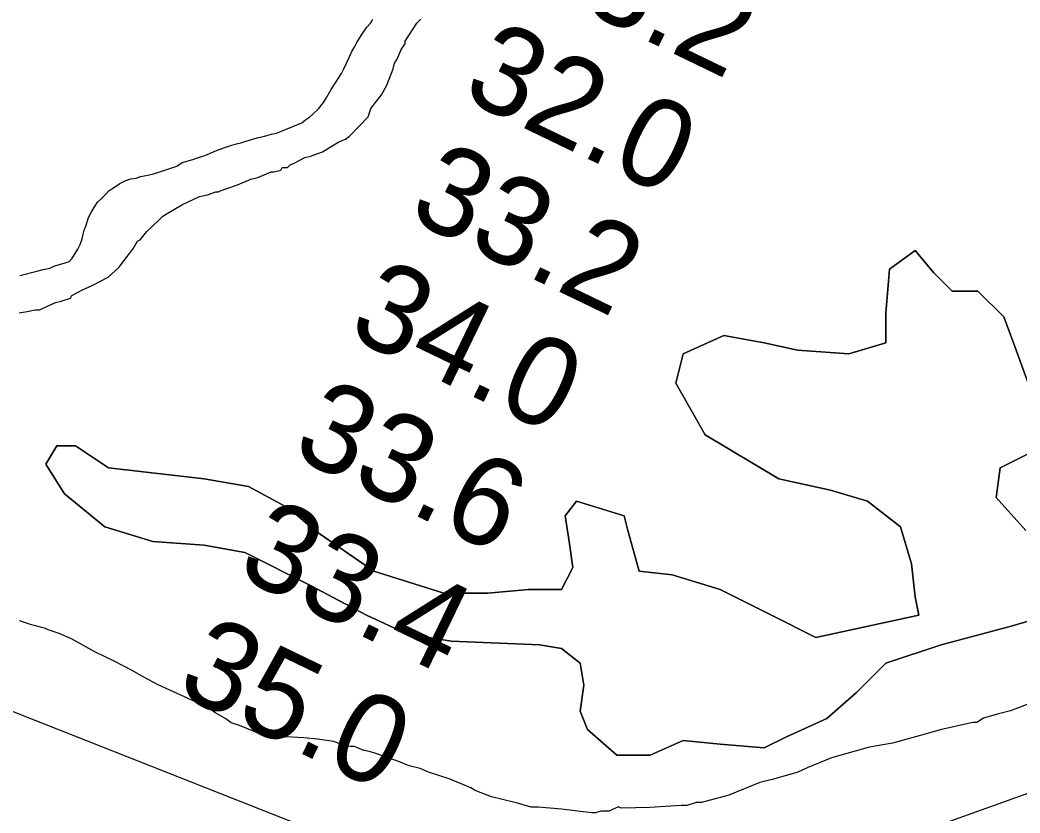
# Model space of a CAD drawing. Extents: x 3219052 to 3256913, y 800770 to 826146.
# Drawn here: x 3237861 to 3238618, y 811124 to 811725 of the extents above; entities that cross this region are included whole.
import ezdxf

# ---------------------------------------------------------------- set-up
doc = ezdxf.new("R2010")
doc.units = 0
for name, color, linetype in [('V-LEVE-TOET', 7, 'Continuous'), ('V-RIVR-RANG', 7, 'Continuous'), ('V-SITE-VEGE', 7, 'Continuous'), ('V-TOPO-SHOR', 7, 'Continuous')]:
    doc.layers.add(name, color=color, linetype=linetype)

msp = doc.modelspace()

# ---------------------------------------------------------------- linework, layer by layer
at = {"layer": 'V-LEVE-TOET'}
for points in [[(3240582.342, 810973.949), (3240012.289, 811195.518), (3239640.372, 811323.9770000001), (3239605.614, 811332.902), (3239570.251, 811345.123), (3239539.09, 811351.06), (3239508.235, 811354.603), (3239472.887, 811357.837), (3239436.0470000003, 811357.175), (3239400.705, 811357.415), (3239363.569, 811355.2540000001), (3239330.921, 811355.199), (3239297.078, 811353.343), (3239268.634, 811348.8030000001), (3239238.991, 811343.361), (3239077.918, 811304.15), (3238719.921, 811173.252), (3238449.923, 811076.349)], [(3238182.165, 811071.7000000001), (3237860.271, 811198.746), (3237814.414, 811217.536), (3237784.448, 811226.4720000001), (3237756.583, 811232.116), (3237732.015, 811236.265), (3237708.346, 811240.419), (3237688.88, 811239.188), (3237662.825, 811237.3470000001), (3237316.042, 811205.908), (3236864.697, 811191.961), (3236556.232, 811171.966), (3236455.3140000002, 811160.1140000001), (3236418.184, 811154.96), (3236209.219, 811099.193)]]:
    msp.add_lwpolyline(points, dxfattribs=at)
at = {"layer": 'V-SITE-VEGE'}
for points in [[(3237860.046, 811502.831), (3237866.214, 811503.98), (3237872.383, 811505.1290000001), (3237875.477, 811505.188), (3237880.595, 811507.349), (3237887.757, 811510.5800000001), (3237891.864, 811511.6900000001), (3237899.046, 811513.89), (3237900.037, 811515.973), (3237908.211, 811520.255), (3237915.373, 811523.4890000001), (3237927.632, 811529.912), (3237935.7460000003, 811537.2880000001), (3237943.803, 811547.762), (3237946.818, 811551.946), (3237949.8140000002, 811557.16), (3237951.858, 811558.231), (3237956.898, 811564.519), (3237966.024, 811572.944), (3237969.059, 811576.1), (3237972.114, 811578.2220000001), (3237983.344, 811584.628), (3237996.633, 811591.071), (3238002.804, 811592.22), (3238008.954, 811594.4010000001), (3238011.0160000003, 811594.4400000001), (3238013.058, 811595.511), (3238025.358, 811599.871), (3238035.594, 811604.192), (3238040.733, 811605.323), (3238050.969, 811609.644), (3238053.0330000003, 811609.683), (3238058.169, 811610.814), (3238059.163, 811612.8960000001), (3238063.287, 811612.974), (3238065.311, 811615.078), (3238068.387, 811616.167), (3238076.558, 811620.452), (3238080.667, 811621.56), (3238089.8910000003, 811624.8300000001), (3238094.988, 811628.023), (3238102.13, 811632.287), (3238107.248, 811634.448), (3238110.303, 811636.569), (3238124.469, 811651.286), (3238126.415, 811657.512), (3238134.47, 811667.986), (3238138.4590000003, 811675.283), (3238143.38, 811687.757), (3238144.335, 811691.904), (3238146.338, 811695.0380000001), (3238149.295, 811702.316), (3238152.312, 811706.5), (3238152.273, 811708.5650000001), (3238161.3000000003, 811722.149), (3238164.336, 811725.3030000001)], [(3238625.039, 811446.734), (3238613.886, 811477.4230000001), (3238605.518, 811499.7440000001), (3238585.994, 811519.274), (3238566.475, 811519.274), (3238552.532, 811533.223), (3238538.5870000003, 811549.964), (3238519.066, 811536.015), (3238516.276, 811502.534), (3238516.276, 811480.215), (3238488.389, 811471.845), (3238449.346, 811474.636), (3238424.245, 811480.215), (3238393.568, 811485.794), (3238362.8910000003, 811471.845), (3238357.315, 811449.525), (3238379.625, 811410.464), (3238435.403, 811376.985), (3238474.444, 811368.617), (3238502.3310000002, 811360.247), (3238527.432, 811340.715), (3238535.798, 811312.817), (3238538.5870000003, 811287.707), (3238541.377, 811273.758), (3238463.288, 811257.018), (3238429.826, 811273.758), (3238390.781, 811293.29), (3238354.525, 811304.447), (3238329.427, 811307.237), (3238321.061, 811337.9280000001), (3238318.271, 811349.085), (3238282.018, 811360.247), (3238273.6520000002, 811349.085), (3238276.4390000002, 811329.558), (3238279.228, 811310.028), (3238270.862, 811293.29), (3238245.762, 811293.29), (3238215.085, 811290.496), (3238181.6210000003, 811290.496), (3238128.633, 811307.237), (3238084.011, 811337.9280000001), (3238064.489, 811354.666), (3238033.812, 811371.407), (3238000.35, 811376.985), (3237927.839, 811385.356), (3237902.74, 811402.096), (3237888.796, 811402.096), (3237880.43, 811388.149), (3237894.372, 811365.826), (3237925.049, 811340.715), (3237961.305, 811329.558), (3238000.35, 811326.7660000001), (3238031.025, 811321.188), (3238081.224, 811296.077), (3238123.054, 811273.758), (3238153.731, 811259.809), (3238187.197, 811254.228), (3238254.128, 811251.439), (3238270.862, 811248.645), (3238284.805, 811237.488), (3238287.594, 811220.748), (3238284.805, 811201.22), (3238290.386, 811187.269), (3238312.6950000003, 811167.7390000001), (3238337.793, 811167.7390000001), (3238362.8910000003, 811178.899), (3238390.781, 811176.109), (3238424.245, 811173.322), (3238440.9790000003, 811181.688), (3238471.656, 811195.639), (3238493.965, 811215.169), (3238516.276, 811237.488), (3238558.109, 811251.439), (3238611.097, 811265.388), (3238658.506, 811279.337)], [(3238329.427, 811307.237), (3238354.525, 811304.447), (3238390.781, 811293.29), (3238429.826, 811273.758), (3238463.288, 811257.018), (3238541.377, 811273.758), (3238538.5870000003, 811287.707), (3238535.798, 811312.817), (3238527.432, 811340.715), (3238502.3310000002, 811360.247), (3238474.444, 811368.617), (3238435.403, 811376.985), (3238379.625, 811410.464), (3238357.315, 811449.525), (3238362.8910000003, 811471.845), (3238393.568, 811485.794), (3238424.245, 811480.215), (3238449.346, 811474.636), (3238488.389, 811471.845), (3238516.276, 811480.215), (3238516.276, 811502.534), (3238519.066, 811536.015), (3238538.5870000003, 811549.964), (3238552.532, 811533.223), (3238566.475, 811519.274), (3238585.994, 811519.274), (3238605.518, 811499.7440000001), (3238613.886, 811477.4230000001), (3238625.039, 811446.734)], [(3238658.506, 811279.337), (3238611.097, 811265.388), (3238558.109, 811251.439), (3238516.276, 811237.488), (3238493.965, 811215.169), (3238471.656, 811195.639), (3238440.9790000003, 811181.688), (3238424.245, 811173.322), (3238390.781, 811176.109), (3238362.8910000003, 811178.899), (3238337.793, 811167.7390000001), (3238312.6950000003, 811167.7390000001), (3238290.386, 811187.269), (3238284.805, 811201.22), (3238287.594, 811220.748), (3238284.805, 811237.488), (3238270.862, 811248.645), (3238254.128, 811251.439), (3238187.197, 811254.228), (3238153.731, 811259.809), (3238123.054, 811273.758), (3238081.224, 811296.077), (3238031.025, 811321.188), (3238000.35, 811326.7660000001), (3237961.305, 811329.558), (3237925.049, 811340.715), (3237894.372, 811365.826), (3237880.43, 811388.149), (3237888.796, 811402.096), (3237902.74, 811402.096), (3237927.839, 811385.356), (3238000.35, 811376.985), (3238033.812, 811371.407), (3238064.489, 811354.666), (3238084.011, 811337.9280000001), (3238128.633, 811307.237), (3238181.6210000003, 811290.496), (3238215.085, 811290.496), (3238245.762, 811293.29), (3238270.862, 811293.29), (3238279.228, 811310.028), (3238276.4390000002, 811329.558), (3238273.6520000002, 811349.085), (3238282.018, 811360.247), (3238318.271, 811349.085), (3238321.061, 811337.9280000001), (3238329.427, 811307.237)], [(3238625.039, 811396.515), (3238602.728, 811385.356), (3238599.941, 811363.036), (3238622.25, 811337.9280000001)], [(3238622.25, 811337.9280000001), (3238599.941, 811363.036), (3238602.728, 811385.356), (3238625.039, 811396.515)], [(3238143.012, 811164.608), (3238131.5840000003, 811168.517), (3238125.358, 811170.463), (3238121.213, 811171.415), (3238113.932, 811174.373), (3238110.838, 811174.313), (3238105.66, 811175.247), (3238098.382, 811178.204), (3238085.963, 811180.031), (3238075.631, 811180.8690000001), (3238062.202, 811181.643), (3238050.856, 811181.43), (3238043.596, 811183.353), (3238026.9560000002, 811190.261), (3238020.728, 811192.207), (3238016.54, 811195.221), (3238008.19, 811200.2220000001), (3238000.874, 811205.242), (3237991.511, 811209.193), (3237965.487, 811221.079), (3237954.026, 811227.051), (3237945.677, 811232.052), (3237932.129, 811239.018), (3237917.552, 811245.965), (3237899.8200000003, 811255.944), (3237890.4590000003, 811259.895), (3237882.15, 811262.832), (3237880.0670000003, 811263.823), (3237868.66, 811266.703), (3237860.3510000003, 811269.639)], [(3238636.375, 811211.134), (3238610.767, 811201.359), (3238601.522, 811199.121), (3238590.236, 811195.809), (3238585.136, 811192.618), (3238582.042, 811192.559), (3238557.386, 811186.931), (3238546.097, 811183.621), (3238521.46, 811176.961), (3238508.09, 811174.645), (3238502.952, 811173.514), (3238475.24, 811165.765), (3238456.81, 811158.191), (3238449.649, 811154.96), (3238438.362, 811151.648), (3238430.15, 811149.43), (3238420.9050000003, 811147.189), (3238397.357, 811137.4550000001), (3238376.828, 811131.905), (3238372.701, 811131.827), (3238365.521, 811129.628), (3238361.394, 811129.5480000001), (3238337.691, 811128.067), (3238316.031, 811127.656), (3238313.946, 811128.647), (3238308.828, 811126.486), (3238306.786, 811125.415), (3238300.595, 811125.2980000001), (3238296.491, 811124.188), (3238293.394, 811124.1290000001), (3238270.6410000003, 811126.791), (3238253.069, 811128.522), (3238247.912, 811128.424), (3238237.539, 811131.322), (3238234.424, 811132.294), (3238217.844, 811136.108), (3238205.367, 811141.029), (3238202.236, 811143.032), (3238185.596, 811149.9400000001), (3238170.023, 811154.804), (3238163.774, 811157.78), (3238155.484, 811159.684), (3238148.2060000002, 811162.6460000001), (3238143.012, 811164.608)]]:
    msp.add_lwpolyline(points, dxfattribs=at)
at = {"layer": 'V-TOPO-SHOR'}
msp.add_lwpolyline([(3237860.779, 811531.052), (3237873.597, 811534.3), (3237878.293, 811535.679), (3237883.428, 811536.635), (3237887.258, 811538.425), (3237894.9420000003, 811540.719), (3237897.93, 811541.632), (3237900.0330000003, 811543.8200000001), (3237904.616, 811551.2050000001), (3237906.267, 811554.672), (3237907.903, 811558.995), (3237908.696, 811562.444), (3237909.497, 811565.4670000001), (3237910.728, 811568.4940000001), (3237912.751, 811574.9720000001), (3237914.815, 811579.305), (3237919.397, 811586.6900000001), (3237922.352, 811589.324), (3237925.719, 811592.822), (3237928.2460000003, 811595.4450000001), (3237931.64, 811597.655), (3237936.303, 811600.75), (3237940.983, 811602.986), (3237944.821, 811604.346), (3237948.6750000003, 811604.85), (3237952.085, 811606.202), (3237957.647, 811607.166), (3237961.9220000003, 811608.106), (3237967.468, 811609.929), (3237971.305, 811611.291), (3237979.411, 811614.0210000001), (3237983.6550000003, 811616.675), (3237991.767, 811618.9770000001), (3237995.177, 811620.331), (3238000.723, 811622.153), (3238009.671, 811625.758), (3238014.359, 811627.564), (3238021.185, 811629.84), (3238024.6010000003, 811630.763), (3238028.019, 811631.687), (3238031.007, 811632.6020000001), (3238040.399, 811635.357), (3238045.953, 811636.752), (3238051.079, 811638.136), (3238054.9250000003, 811639.068), (3238058.7630000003, 811640.43), (3238061.741, 811641.773), (3238066.001, 811643.571), (3238074.099, 811646.732), (3238077.062, 811648.933), (3238080.026, 811651.137), (3238082.559, 811653.332), (3238086.778, 811657.277), (3238090.5500000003, 811662.071), (3238092.631, 811665.544), (3238096.3710000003, 811672.055), (3238101.374, 811679.878), (3238104.296, 811684.226), (3238105.947, 811687.692), (3238108.012, 811692.025), (3238110.076, 811696.357), (3238112.14, 811700.6900000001), (3238114.213, 811704.594), (3238115.872, 811707.631), (3238119.208, 811712.845), (3238123.378, 811719.3640000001), (3238126.325, 811722.426), (3238127.992, 811725.033)], dxfattribs=at)

# ---------------------------------------------------------------- texts
at = {"layer": 'V-RIVR-RANG'}
for s, p in [('33.2', (3238239.51559604, 811755.206551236)), ('32.0', (3238193.6396297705, 811666.311115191)), ('33.2', (3238152.98859604, 811574.892551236)), ('34.0', (3238107.1126297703, 811485.997115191)), ('33.6', (3238064.799799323, 811395.3813646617)), ('33.4', (3238023.19959604, 811304.421551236)), ('35.0', (3237977.3226297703, 811215.526115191))]:
    msp.add_text(s, height=67.00000000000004, rotation=334.22832571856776, dxfattribs=at).set_placement(p)

doc.saveas('drawing.dxf')
